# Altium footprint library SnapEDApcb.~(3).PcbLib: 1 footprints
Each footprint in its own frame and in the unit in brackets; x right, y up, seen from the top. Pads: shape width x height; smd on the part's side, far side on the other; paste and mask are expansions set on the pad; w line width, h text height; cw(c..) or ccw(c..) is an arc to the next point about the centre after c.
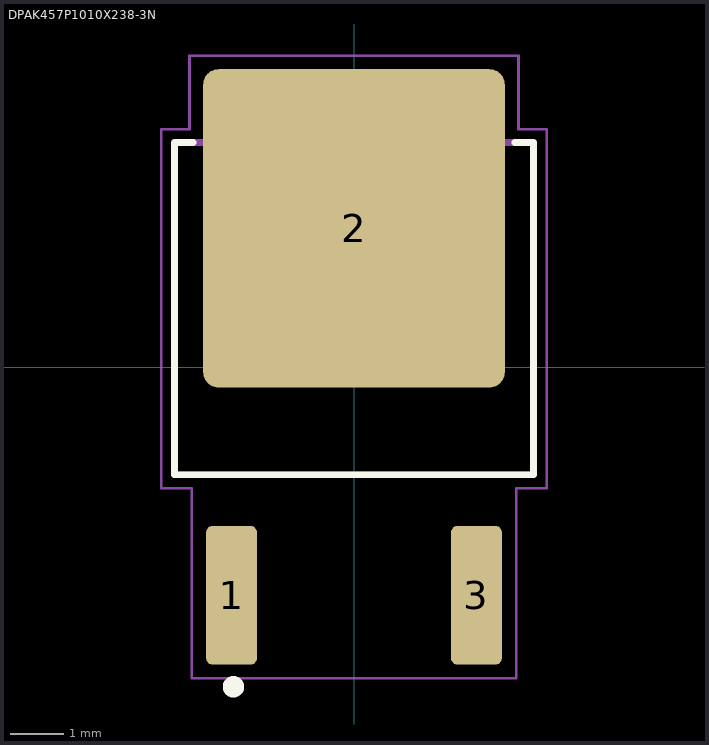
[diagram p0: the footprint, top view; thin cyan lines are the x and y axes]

## DPAK457P1010X238-3N [mm]
pads (3):
  rrect25% 0.95x2.59 smd: 1(-2.286,-4.26) 3(2.286,-4.26)
  rrect10% 5.63x5.94 smd: 2(0,2.59)
Top Overlay:
  circle w0.2: c-2.25,-5.969 r0.1
  lines w0.127: -3,4.19 -3.35,4.19 -3.35,-2.01 3.35,-2.01 3.35,4.19 3,4.19
Mechanical 13:
  lines w0.127: -3.35,-2.01 -3.35,4.19 3.35,4.19 3.35,-2.01 -3.35,-2.01
Mechanical 15:
  lines w0.05: -3.6,-2.26 -3.03,-2.26 -3.03,-5.81 3.03,-5.81 3.03,-2.26 3.6,-2.26 3.6,4.44 3.07,4.44 3.07,5.81 -3.07,5.81 -3.07,4.44 -3.6,4.44 -3.6,-2.26
3D body "User Library-TO252-2_TO252-22.sldprt": height 1.57, standoff 1.07, extent 1.886,-2.667 2.686,-1.667
3D body "User Library-TO252-2_TO252-22.sldprt": height 1.57, standoff 1.07, extent -2.667,-2.659 -1.867,-1.659
3D body "User Library-TO252-2_TO252-25.sldprt": height 0.5, standoff 0, extent -2.725,0.21 2.725,5.42
3D body "User Library-TO252-2_TO252-24.sldprt": height 1.57, standoff 0, extent -2.667,-5.307 -1.867,-2.567
3D body "User Library-TO252-2_TO252-23.sldprt": height 1.57, standoff 0, extent 1.886,-5.407 2.686,-2.667
3D body "User Library-TO252-2_TO252-22.sldprt": height 1.57, standoff 1.07, extent -0.292,-2.913 0.508,-1.913
3D body "User Library-TO252-2_TO252-21.sldprt": height 2.29, standoff 0, extent -3.278,-1.907 3.302,4.193
3D body: height 0.25, standoff 0, extent 0,0 0,0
